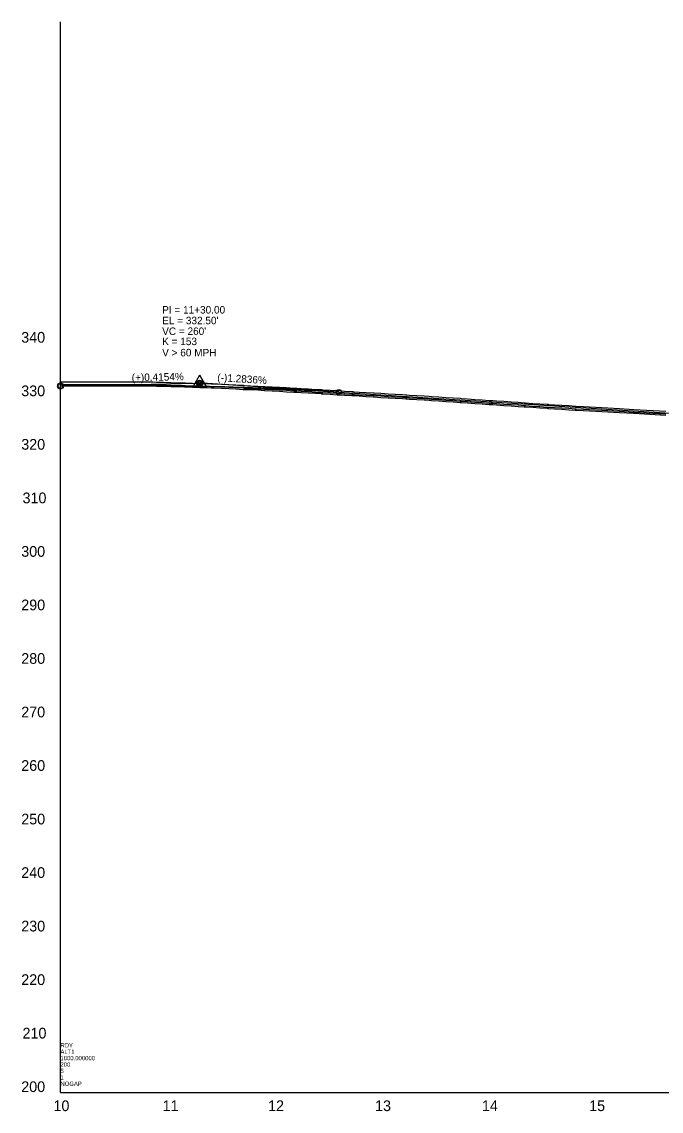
# Model space of a CAD drawing. Extents: x 2111382 to 2119088, y 667477 to 672158.
# Drawn here: x 2112691 to 2113288, y 670803 to 671820 of the extents above; entities that cross this region are included whole.
import ezdxf

# ---------------------------------------------------------------- set-up
doc = ezdxf.new("R2010")
doc.units = 0
for name, color, linetype in [('Exist Profile Cell', 7, 'Continuous'), ('Exist Vertical Profile Ground Line', 7, 'Continuous'), ('Exist Vertical Profile Horizontal Axis Label Major', 7, 'Continuous'), ('Exist Vertical Profile Vertical Axis Label', 7, 'Continuous'), ('Prop PFL VPI Symbol CELL', 7, 'Continuous'), ('Prop Vertical Profile Curve Label', 7, 'Continuous'), ('Prop Vertical Profile Grade', 7, 'Continuous'), ('Prop Vertical Profile Grade Label', 7, 'Continuous'), ('Prop VPI Label', 7, 'Continuous'), ('Scratch_Level_2', 7, 'Continuous'), ('Scratch_Level_3', 7, 'Continuous')]:
    doc.layers.add(name, color=color, linetype=linetype)

msp = doc.modelspace()

# ---------------------------------------------------------------- linework, layer by layer
at = {"layer": 'Exist Profile Cell'}
for q in [(2112726.7, 671820.2), (2114983.3, 670820.2), (2112726.7, 670820.2)]:
    msp.add_line((2112726.7, 670820.2), q, dxfattribs=at)
at = {"layer": 'Exist Vertical Profile Ground Line'}
for points in [[(2112726.7, 671480), (2112756.8, 671480.1), (2112762.2, 671480.1), (2112769, 671480.1), (2112775.7, 671480.1), (2112782.5, 671480.1), (2112786.3, 671480.1), (2112786.8, 671480.1), (2112789.2, 671480.1), (2112796, 671480.1), (2112802.7, 671480.1), (2112809.5, 671480.1), (2112813.1, 671480.1), (2112816.3, 671480), (2112823, 671479.8), (2112829.8, 671479.6), (2112836.5, 671479.4), (2112842.4, 671479.2), (2112843.3, 671479.1), (2112850.1, 671478.9), (2112856.8, 671478.7), (2112863.6, 671478.5), (2112867.8, 671478.4), (2112868.2, 671478.4), (2112868.7, 671478.3), (2112870.3, 671478.3), (2112877.1, 671477.9), (2112883.9, 671477.6), (2112890.6, 671477.3), (2112897.4, 671476.9), (2112898.2, 671476.9), (2112904.1, 671476.6), (2112910.9, 671476.3), (2112917.3, 671475.9), (2112917.7, 671475.9), (2112924.4, 671475.5), (2112931.2, 671475.1), (2112937.9, 671474.7), (2112944.7, 671474.3), (2112946.7, 671474.2), (2112947.4, 671474.2), (2112951.4, 671474), (2112958.2, 671473.6), (2112965, 671473.2), (2112970.1, 671472.9), (2112970.6, 671472.8), (2112971.7, 671472.8), (2112978.5, 671472.3), (2112985.2, 671471.9), (2112992, 671471.5), (2112998.8, 671471.1), (2112999.8, 671471), (2113000.6, 671471), (2113005.5, 671470.7), (2113012.3, 671470.3), (2113019, 671469.9), (2113019.4, 671469.8), (2113019.8, 671469.8), (2113025.8, 671469.4), (2113032.6, 671469), (2113039.3, 671468.6), (2113046.1, 671468.2), (2113049.1, 671468), (2113049.8, 671468), (2113050.2, 671468), (2113052.8, 671467.8), (2113059.6, 671467.4), (2113066.3, 671467), (2113070.9, 671466.7), (2113073.1, 671466.6), (2113079.9, 671466.1), (2113086.6, 671465.6), (2113093.4, 671465.2), (2113100.1, 671464.7), (2113100.9, 671464.7), (2113106.9, 671464.2), (2113113.7, 671463.8), (2113120.4, 671463.3), (2113127.2, 671462.8), (2113130, 671462.7), (2113130.5, 671462.6), (2113133.9, 671462.4), (2113140.7, 671461.9), (2113147.5, 671461.5), (2113154.2, 671461), (2113159.7, 671460.6), (2113160.5, 671460.6), (2113161, 671460.5), (2113167.7, 671460.1), (2113174.5, 671459.6), (2113181.3, 671459.2), (2113182.1, 671459.1), (2113182.6, 671459.1), (2113188, 671458.7), (2113194.8, 671458.3), (2113201.5, 671457.9), (2113207.3, 671457.6), (2113207.7, 671457.6), (2113208.4, 671457.5), (2113215, 671457.1), (2113237.9, 671455.9)], [(2113237.9, 671455.9), (2113248.9, 671455.2), (2113262.2, 671454.5), (2113291.9, 671452.7)]]:
    msp.add_lwpolyline(points, dxfattribs=at)
at = {"layer": 'Prop PFL VPI Symbol CELL'}
for p, q in [((2112856.7, 671490.2), (2112850.2, 671479)), ((2112856.7, 671490.2), (2112863.2, 671479)), ((2112850.2, 671479), (2112863.2, 671479))]:
    msp.add_line(p, q, dxfattribs=at)
for radius in [1.75, 1.2]:
    msp.add_circle((2112856.7, 671482.7), radius, dxfattribs=at)
at = {"layer": 'Prop Vertical Profile Curve Label'}
for centre in [(2112726.7, 671480), (2112986.7, 671474.4)]:
    msp.add_circle(centre, 2.25, dxfattribs=at)
at = {"layer": 'Prop Vertical Profile Grade'}
msp.add_line((2112986.7, 671474.4), (2113481.7, 671442.6), dxfattribs=at)
msp.add_spline([(2112726.7, 671480), (2112731.9, 671480.1), (2112737.1, 671480.2), (2112742.3, 671480.3), (2112747.5, 671480.4), (2112752.7, 671480.5), (2112757.9, 671480.5), (2112763.1, 671480.6), (2112768.3, 671480.6), (2112773.5, 671480.6), (2112778.7, 671480.7), (2112783.9, 671480.7), (2112789.1, 671480.7), (2112794.3, 671480.7), (2112799.5, 671480.7), (2112804.7, 671480.7), (2112809.9, 671480.6), (2112815.1, 671480.6), (2112820.3, 671480.5), (2112825.5, 671480.5), (2112830.7, 671480.4), (2112835.9, 671480.4), (2112841.1, 671480.3), (2112846.3, 671480.2), (2112851.5, 671480.1), (2112856.7, 671480), (2112861.9, 671479.9), (2112867.1, 671479.7), (2112872.3, 671479.6), (2112877.5, 671479.5), (2112882.7, 671479.3), (2112887.9, 671479.1), (2112893.1, 671479), (2112898.3, 671478.8), (2112903.5, 671478.6), (2112908.7, 671478.4), (2112913.9, 671478.2), (2112919.1, 671478), (2112924.3, 671477.8), (2112929.5, 671477.5), (2112934.7, 671477.3), (2112939.9, 671477), (2112945.1, 671476.8), (2112950.3, 671476.5), (2112955.5, 671476.2), (2112960.7, 671475.9), (2112965.9, 671475.7), (2112971.1, 671475.4), (2112976.3, 671475), (2112981.5, 671474.7), (2112986.7, 671474.4)], degree=3, dxfattribs=at)
at = {"layer": 'Prop VPI Label'}
for p, q in [((2112726.7, 671480), (2112853.9, 671482.7)), ((2112986.7, 671474.4), (2112859.4, 671482.6))]:
    msp.add_line(p, q, dxfattribs=at)
for centre in [(2112726.7, 671480), (2112856.7, 671482.7)]:
    msp.add_circle(centre, 2.75, dxfattribs=at)
at = {"layer": 'Scratch_Level_2'}
for points in [[(2112726.7, 671481.3), (2112756.8, 671481.3), (2112762.2, 671481.3), (2112769, 671481.3), (2112775.7, 671481.3), (2112782.5, 671481.3), (2112786.3, 671481.3), (2112786.8, 671481.3), (2112789.2, 671481.3), (2112796, 671481.3), (2112802.7, 671481.3), (2112809.5, 671481.3), (2112813.1, 671481.3), (2112816.3, 671481.2), (2112823, 671481), (2112829.8, 671480.8), (2112836.5, 671480.6), (2112842.4, 671480.4), (2112843.3, 671480.4), (2112850.1, 671480.2), (2112856.8, 671480), (2112863.6, 671479.8), (2112867.8, 671479.6), (2112868.2, 671479.6), (2112868.7, 671479.6), (2112870.3, 671479.5), (2112877.1, 671479.2), (2112883.9, 671478.9), (2112890.6, 671478.5), (2112897.4, 671478.2), (2112898.2, 671478.1), (2112904.1, 671477.8), (2112910.9, 671477.5), (2112917.3, 671477.2), (2112917.7, 671477.2), (2112924.4, 671476.8), (2112931.2, 671476.4), (2112937.9, 671476), (2112944.7, 671475.6), (2112946.7, 671475.5), (2112947.4, 671475.4), (2112951.4, 671475.2), (2112958.2, 671474.8), (2112965, 671474.4), (2112970.1, 671474.1), (2112970.6, 671474.1), (2112971.7, 671474), (2112978.5, 671473.6), (2112985.2, 671473.2), (2112992, 671472.8), (2112998.8, 671472.4), (2112999.8, 671472.3), (2113000.6, 671472.2), (2113005.5, 671471.9), (2113012.3, 671471.5), (2113019, 671471.1), (2113019.4, 671471.1), (2113019.8, 671471.1), (2113025.8, 671470.7), (2113032.6, 671470.3), (2113039.3, 671469.9), (2113046.1, 671469.5), (2113049.1, 671469.3), (2113049.8, 671469.2), (2113050.2, 671469.2), (2113052.8, 671469.1), (2113059.6, 671468.6), (2113066.3, 671468.2), (2113070.9, 671468), (2113073.1, 671467.8), (2113079.9, 671467.4), (2113086.6, 671466.9), (2113093.4, 671466.4), (2113100.1, 671466), (2113100.9, 671465.9), (2113106.9, 671465.5), (2113113.7, 671465), (2113120.4, 671464.6), (2113127.2, 671464.1), (2113130, 671463.9), (2113130.5, 671463.9), (2113133.9, 671463.6), (2113140.7, 671463.2), (2113147.5, 671462.7), (2113154.2, 671462.3), (2113159.7, 671461.9), (2113160.5, 671461.8), (2113161, 671461.8), (2113167.7, 671461.3), (2113174.5, 671460.9), (2113181.3, 671460.4), (2113182.1, 671460.4), (2113182.6, 671460.3), (2113188, 671460), (2113194.8, 671459.6), (2113201.5, 671459.2), (2113207.3, 671458.8), (2113207.7, 671458.8), (2113208.4, 671458.8), (2113215, 671458.4), (2113237.9, 671457.1)], [(2113237.9, 671457.1), (2113248.9, 671456.5), (2113262.2, 671455.7), (2113291.9, 671453.9)]]:
    msp.add_lwpolyline(points, dxfattribs=at)
at = {"layer": 'Scratch_Level_3'}
for points in [[(2112726.7, 671483.8), (2112756.8, 671483.8), (2112762.2, 671483.8), (2112769, 671483.8), (2112775.7, 671483.8), (2112782.5, 671483.8), (2112786.3, 671483.8), (2112786.8, 671483.8), (2112789.2, 671483.8), (2112796, 671483.8), (2112802.7, 671483.8), (2112809.5, 671483.8), (2112813.1, 671483.8), (2112816.3, 671483.7), (2112823, 671483.5), (2112829.8, 671483.3), (2112836.5, 671483.1), (2112842.4, 671482.9), (2112843.3, 671482.9), (2112850.1, 671482.7), (2112856.8, 671482.5), (2112863.6, 671482.3), (2112867.8, 671482.1), (2112868.2, 671482.1), (2112868.7, 671482.1), (2112870.3, 671482), (2112877.1, 671481.7), (2112883.9, 671481.4), (2112890.6, 671481), (2112897.4, 671480.7), (2112898.2, 671480.6), (2112904.1, 671480.3), (2112910.9, 671480), (2112917.3, 671479.7), (2112917.7, 671479.7), (2112924.4, 671479.3), (2112931.2, 671478.9), (2112937.9, 671478.5), (2112944.7, 671478.1), (2112946.7, 671478), (2112947.4, 671477.9), (2112951.4, 671477.7), (2112958.2, 671477.3), (2112965, 671476.9), (2112970.1, 671476.6), (2112970.6, 671476.6), (2112971.7, 671476.5), (2112978.5, 671476.1), (2112985.2, 671475.7), (2112992, 671475.3), (2112998.8, 671474.9), (2112999.8, 671474.8), (2113000.6, 671474.7), (2113005.5, 671474.4), (2113012.3, 671474), (2113019, 671473.6), (2113019.4, 671473.6), (2113019.8, 671473.6), (2113025.8, 671473.2), (2113032.6, 671472.8), (2113039.3, 671472.4), (2113046.1, 671472), (2113049.1, 671471.8), (2113049.8, 671471.7), (2113050.2, 671471.7), (2113052.8, 671471.6), (2113059.6, 671471.1), (2113066.3, 671470.7), (2113070.9, 671470.5), (2113073.1, 671470.3), (2113079.9, 671469.9), (2113086.6, 671469.4), (2113093.4, 671468.9), (2113100.1, 671468.5), (2113100.9, 671468.4), (2113106.9, 671468), (2113113.7, 671467.5), (2113120.4, 671467.1), (2113127.2, 671466.6), (2113130, 671466.4), (2113130.5, 671466.4), (2113133.9, 671466.1), (2113140.7, 671465.7), (2113147.5, 671465.2), (2113154.2, 671464.8), (2113159.7, 671464.4), (2113160.5, 671464.3), (2113161, 671464.3), (2113167.7, 671463.8), (2113174.5, 671463.4), (2113181.3, 671462.9), (2113182.1, 671462.9), (2113182.6, 671462.8), (2113188, 671462.5), (2113194.8, 671462.1), (2113201.5, 671461.7), (2113207.3, 671461.3), (2113207.7, 671461.3), (2113208.4, 671461.3), (2113215, 671460.9), (2113237.9, 671459.6)], [(2113237.9, 671459.6), (2113248.9, 671459), (2113262.2, 671458.2), (2113291.9, 671456.4)]]:
    msp.add_lwpolyline(points, dxfattribs=at)

# ---------------------------------------------------------------- texts
at = {"layer": 'Exist Profile Cell'}
for s, p in [('ALT1', (2112726.7, 670856.2)), ('RDY', (2112726.7, 670862.2)), ('1000.000000', (2112726.7, 670850.2)), ('200', (2112726.7, 670844.2)), ('5', (2112726.7, 670838.2)), ('1', (2112726.7, 670832.2)), ('NOGAP', (2112726.7, 670826.2))]:
    msp.add_text(s, height=4, dxfattribs=at).set_placement(p)
at = {"layer": 'Exist Vertical Profile Horizontal Axis Label Major'}
for s, p in [('10', (2112720.2, 670802.7)), ('11', (2112822.1, 670802.7)), ('12', (2112920.6, 670802.7)), ('13', (2113020.5, 670802.7)), ('14', (2113120.3, 670802.7)), ('15', (2113220.4, 670802.7))]:
    msp.add_text(s, height=10, dxfattribs=at).set_placement(p)
at = {"layer": 'Exist Vertical Profile Vertical Axis Label'}
for s, p in [('340', (2112690.1, 671520.5)), ('330', (2112690.1, 671470.5)), ('320', (2112690.1, 671420.5)), ('310', (2112691.3, 671370.5)), ('300', (2112690.1, 671320.5)), ('290', (2112690.1, 671270.5)), ('280', (2112690.1, 671220.5)), ('270', (2112690.1, 671170.5)), ('260', (2112690.1, 671120.5)), ('250', (2112690.1, 671070.5)), ('240', (2112690.1, 671020.5)), ('230', (2112690.1, 670970.5)), ('220', (2112690.1, 670920.5)), ('210', (2112691.3, 670870.5)), ('200', (2112690.1, 670820.5))]:
    msp.add_text(s, height=10, dxfattribs=at).set_placement(p)
at = {"layer": 'Prop Vertical Profile Curve Label'}
for s, p in [("VC = 260'", (2112821.7, 671527.7)), ('K = 153', (2112821.7, 671518.2)), ('V > 60 MPH', (2112821.7, 671507.7))]:
    msp.add_text(s, height=7, dxfattribs=at).set_placement(p)
at = {"layer": 'Prop Vertical Profile Grade Label'}
for s, rotation, p in [('(+)0.4154%', 1.1898, (2112793.3, 671484.4)), ('(-)1.2836%', 356.3278, (2112873, 671484.7))]:
    msp.add_text(s, height=7, rotation=rotation, dxfattribs=at).set_placement(p)
at = {"layer": 'Prop VPI Label'}
for s, p in [('PI = 11+30.00', (2112821.7, 671547.7)), ("EL = 332.50'", (2112821.7, 671537.7))]:
    msp.add_text(s, height=7, dxfattribs=at).set_placement(p)

doc.saveas('drawing.dxf')
